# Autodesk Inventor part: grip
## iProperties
Author: Administrator
Created: 2001-04
Part Number: grip
Document SubType Name: Modeling
Designer: Administrator
Control State: 0
Master: False
Checked Out: False
PropertySet Name: Design Tracking Control
Shininess: 5.0
PropertySet Name: _Private Model Information
Density: 0.0
Volumn: 0.0
Area: 0.0
PropertySet Name: Model Information
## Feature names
1. Revolution1
2. Hole1
